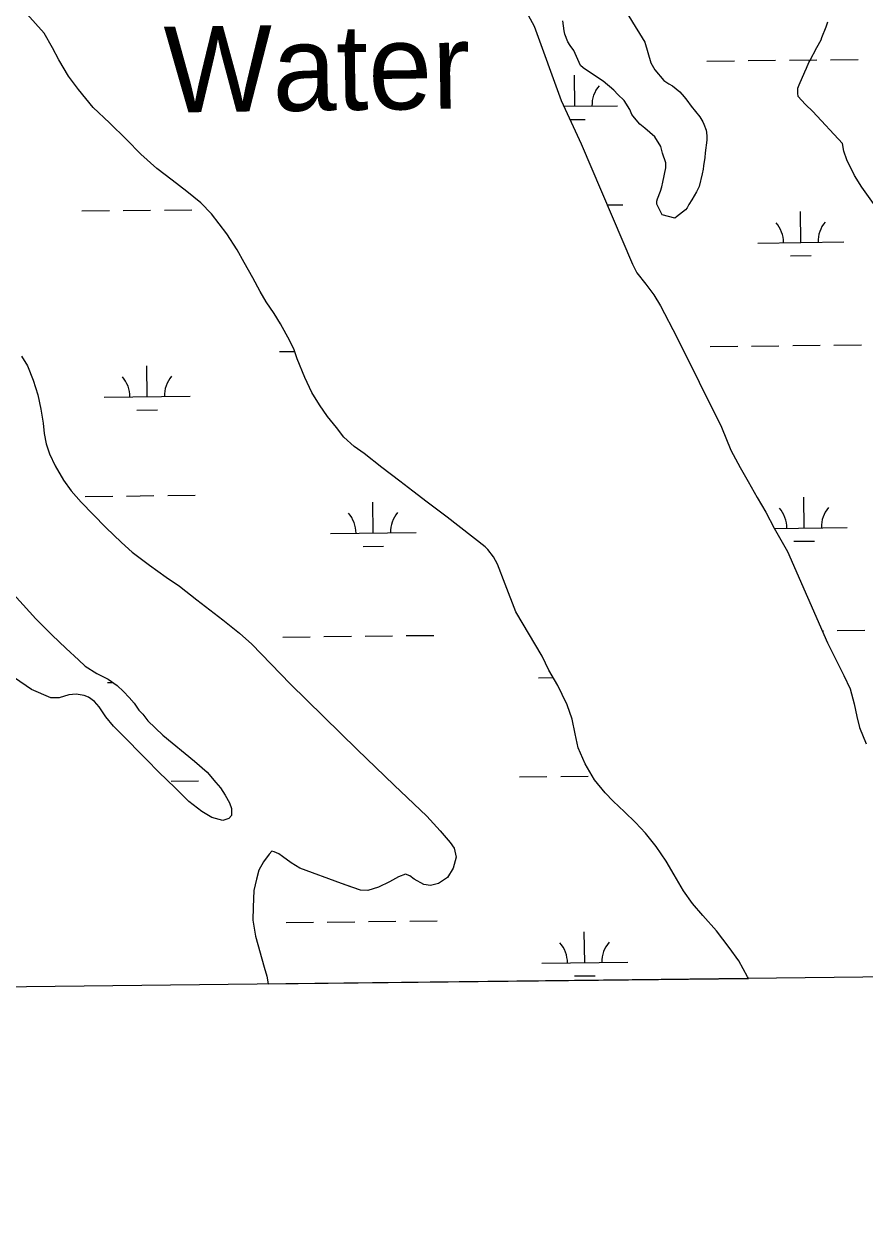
# Model space of a CAD drawing. Extents: x 3683613 to 3738215, y 469626 to 495384.
# Drawn here: x 3712781 to 3713760, y 475040 to 476452 of the extents above; entities that cross this region are included whole.
import ezdxf

# ---------------------------------------------------------------- set-up
doc = ezdxf.new("R2010")
doc.units = 0
for name, color, linetype in [('V-GRID-FRAM', 7, 'Continuous'), ('V-RIVR-IDEN', 7, 'Continuous'), ('V-SITE-VEGE', 7, 'Continuous'), ('V-TOPO-SHOR', 7, 'Continuous'), ('V-WETL-SWMP', 7, 'Continuous')]:
    doc.layers.add(name, color=color, linetype=linetype)

msp = doc.modelspace()

# ---------------------------------------------------------------- linework, layer by layer
at = {"layer": 'V-GRID-FRAM'}
msp.add_lwpolyline([(3687651.7, 493221.8), (3719350.3, 493590.7), (3719569.8, 475409.4), (3687855.3, 475040.3), (3687651.7, 493221.8)], dxfattribs=at)
at = {"layer": 'V-SITE-VEGE'}
for p, q in [((3713714.6, 476448.8), (3713716.7, 476454.7)), ((3713709.7, 476436.7), (3713714.6, 476448.8)), ((3713695.6, 476409.3), (3713703.9, 476425.1)), ((3713703.9, 476425.1), (3713708.8, 476433.7)), ((3713708.8, 476433.7), (3713709.7, 476436.7)), ((3713683, 476381.4), (3713689.8, 476396.7)), ((3713689.8, 476396.7), (3713691.5, 476400.9)), ((3713691.5, 476400.9), (3713694.4, 476407.3)), ((3713694.4, 476407.3), (3713695.6, 476409.3)), ((3713681.4, 476371.6), (3713681.6, 476377.5)), ((3713682.1, 476367.7), (3713681.4, 476371.6)), ((3713681.6, 476377.5), (3713683, 476381.4)), ((3713685.9, 476363.5), (3713682.1, 476367.7)), ((3713690.6, 476358.6), (3713685.9, 476363.5)), ((3713699, 476350.5), (3713690.6, 476358.6)), ((3713733.7, 476313.1), (3713699, 476350.5)), ((3713735.2, 476304.3), (3713733.7, 476313.1)), ((3713738.7, 476294.2), (3713735.2, 476304.3)), ((3713747.7, 476275.8), (3713738.7, 476294.2)), ((3713756.1, 476262.1), (3713747.7, 476275.8)), ((3713769.8, 476243.3), (3713756.1, 476262.1))]:
    msp.add_line(p, q, dxfattribs=at)
msp.add_lwpolyline([(3713477.3, 476473.5), (3713492, 476449.3), (3713497.2, 476441.4), (3713503.4, 476431.2), (3713510.4, 476406.9), (3713514.9, 476398.8), (3713525.6, 476386.5), (3713531.3, 476382.6), (3713535.5, 476380.2), (3713544.1, 476373.4), (3713549.3, 476367.3), (3713552.3, 476363.6), (3713557.5, 476356.7), (3713567.4, 476344), (3713570.9, 476338.1), (3713572.2, 476335.7), (3713574.7, 476328.6), (3713575.2, 476325.9), (3713575.5, 476321.4), (3713575.5, 476316.8), (3713573.6, 476302.2), (3713573.4, 476296.6), (3713571.7, 476287), (3713571.5, 476283.3), (3713570.1, 476277.6), (3713566.7, 476262.8), (3713563.6, 476256.7), (3713558.2, 476247.3), (3713554.8, 476241.8), (3713552.6, 476238.1), (3713550.7, 476235.9), (3713540.2, 476227.5), (3713538.2, 476226.2), (3713523.4, 476229.8), (3713517.4, 476242.3), (3713517.4, 476245.8), (3713518.1, 476248.7), (3713521.8, 476257.6), (3713523.2, 476262.5), (3713524.2, 476268), (3713527.7, 476284.5), (3713527.7, 476290.6), (3713523.9, 476301.7), (3713522.2, 476309.5), (3713514.9, 476321), (3713503.3, 476331), (3713497.6, 476335.4), (3713491.2, 476343), (3713488.2, 476346.9), (3713486, 476352.6), (3713479.2, 476363.1), (3713472.1, 476370.2), (3713467.1, 476375.3), (3713454.7, 476385.8), (3713448.1, 476390), (3713431.5, 476401.2), (3713428.3, 476403.8), (3713420.8, 476421.5), (3713416.6, 476427.4), (3713413.9, 476431.5), (3713410.4, 476440.6), (3713409.3, 476444.5), (3713408, 476456.1)], dxfattribs=at)
at = {"layer": 'V-TOPO-SHOR'}
for points in [[(3713317, 476555.5), (3713374.6, 476449.9), (3713406.1, 476363.1), (3713429.3, 476312.6), (3713489.2, 476172.6), (3713494, 476162.4), (3713504.4, 476149), (3713514, 476136.8), (3713521.6, 476123.8), (3713540.8, 476087.2), (3713592.6, 475982.7), (3713603.4, 475955.9), (3713614.6, 475935.4), (3713623.8, 475919.3), (3713634.3, 475900.7), (3713644.3, 475883.4), (3713653.9, 475864.9), (3713669.5, 475837.7), (3713716.1, 475731.2), (3713735.3, 475693), (3713742.6, 475677.6), (3713747.4, 475660.2), (3713750.3, 475645.2), (3713753.5, 475632.6), (3713761.2, 475613.7)], [(3713317.5, 475843.2), (3713273.3, 475877.7), (3713249.9, 475895), (3713233.2, 475907.9), (3713218.1, 475919.7), (3713197, 475935.7), (3713176.3, 475951.8), (3713164.8, 475960), (3713152.8, 475971), (3713144.1, 475982), (3713133.7, 475995), (3713124.5, 476008.4), (3713115.7, 476023), (3713107.3, 476040.3), (3713098.4, 476062), (3713094.8, 476072.7), (3713090, 476083.3), (3713079.2, 476103), (3713071.6, 476114.8), (3713062.4, 476128.6), (3713055.2, 476140.4), (3713046.8, 476156.6), (3713036.8, 476174.3), (3713028.4, 476189.3), (3713016.4, 476207.8), (3712998.8, 476231), (3712986.1, 476244), (3712969.8, 476257.3), (3712952.7, 476270.2), (3712935.2, 476284), (3712916.5, 476300.8), (3712899.7, 476317.7), (3712879.8, 476337), (3712860.7, 476355), (3712843.6, 476375.9), (3712832, 476391.6), (3712820.8, 476410.5), (3712813.6, 476424.7), (3712803.6, 476441.7), (3712783.6, 476464.1)], [(3712777.5, 476065.2), (3712784.3, 476053.8), (3712791.1, 476037.2), (3712796.4, 476020.3), (3712800, 476003.3), (3712802.5, 475987.2), (3712803.8, 475975.3), (3712806.2, 475963.1), (3712809.9, 475951.3), (3712816.7, 475937.5), (3712826.3, 475920.6), (3712835.4, 475908.4), (3712847, 475895.1), (3712860.9, 475880.6), (3712875.6, 475865.7), (3712893.9, 475848), (3712906.2, 475836.7), (3712926.4, 475821.8), (3712945.9, 475807.7), (3712961.3, 475797.2), (3712981.6, 475781.5), (3713011.7, 475758), (3713031.2, 475742.4), (3713045.5, 475729.8), (3713090.4, 475683.5), (3713168.3, 475607.1), (3713211.6, 475565.5), (3713249.4, 475529.1), (3713264.9, 475512.2), (3713276.8, 475498.5), (3713281.2, 475491.8), (3713283.7, 475481.5), (3713280.2, 475468.5), (3713273.6, 475457.8), (3713262.9, 475450.6), (3713253.9, 475448.6), (3713246, 475449.7), (3713234.9, 475455.9), (3713229.7, 475459.9), (3713224.6, 475461.8), (3713216.3, 475458.6), (3713206.1, 475452.6), (3713193.1, 475446.6), (3713180.9, 475442.6), (3713172.2, 475442.9), (3713161.1, 475446.8), (3713150, 475450.6), (3713101.7, 475468.5), (3713091.4, 475474.7), (3713081.5, 475482.1), (3713077.2, 475485.3), (3713071.6, 475487.6), (3713068.8, 475488.4), (3713065.7, 475484.8), (3713059.4, 475476.1), (3713054, 475466.2), (3713050.9, 475455.9), (3713047.8, 475442.8), (3713047.2, 475423.1), (3713046.9, 475408.1), (3713049.8, 475389.5), (3713059.9, 475353.3), (3713063.1, 475342.7), (3713064.6, 475333.7)], [(3713353.2, 475767.5), (3713340.7, 475799.5), (3713331.8, 475822.7), (3713327, 475831.4), (3713320.6, 475840.1), (3713317.5, 475843.2)], [(3712760.6, 475796.2), (3712794, 475759), (3712812.7, 475740.5), (3712829.5, 475724.8), (3712843.8, 475711.4), (3712851.7, 475704.2), (3712865.3, 475695.5), (3712878.3, 475688.9), (3712888.8, 475681.4), (3712896.1, 475674.5), (3712902.7, 475667.7), (3712908.8, 475660.8), (3712913.9, 475652.9), (3712918.6, 475647.9), (3712924.4, 475640.4), (3712942.1, 475623.5), (3712978.9, 475593.2), (3712993.8, 475580.6), (3713003.6, 475568.4), (3713009, 475562.2), (3713014.5, 475553.7), (3713019.6, 475544.9), (3713021.8, 475538.3), (3713021.8, 475536.4), (3713021.9, 475530.1), (3713018.7, 475526.6), (3713011.8, 475524.3), (3712999.2, 475527.7), (3712987.5, 475534.6), (3712972.3, 475546.5), (3712956.4, 475562.4), (3712937.4, 475580.6), (3712922.8, 475595.3), (3712912.3, 475605.9), (3712903.1, 475615.6), (3712894.2, 475624.4), (3712884.7, 475634.1), (3712875.8, 475645.1), (3712867.8, 475656.7), (3712862.4, 475663), (3712855.4, 475668), (3712850.4, 475669.8), (3712841.2, 475671.3), (3712832.7, 475670.6), (3712821.1, 475667.1), (3712811.6, 475667), (3712788.9, 475676.7), (3712769.2, 475690.4)], [(3713624.3, 475340.2), (3713623, 475342.2), (3713613, 475360.7), (3713601.8, 475376.1), (3713586.7, 475395.8), (3713571.1, 475413.4), (3713558.8, 475427.6), (3713548.4, 475442.2), (3713537.6, 475460.7), (3713528.4, 475476.8), (3713516.4, 475493.8), (3713504, 475509.5), (3713492.5, 475521.7), (3713479.7, 475534.2), (3713466.6, 475546.8), (3713457, 475556.6), (3713444.7, 475571.6), (3713433.9, 475590.1), (3713425.8, 475609), (3713422.2, 475625.2), (3713418.9, 475642.2), (3713412.8, 475658.8), (3713407.2, 475671), (3713402, 475681.6), (3713391.6, 475699.4), (3713384, 475715.5), (3713353.2, 475767.5)]]:
    msp.add_lwpolyline(points, dxfattribs=at)
at = {"layer": 'V-WETL-SWMP'}
for p, q in [((3713317, 476555.5), (3713374.6, 476449.9)), ((3712803.6, 476441.7), (3712783.6, 476464.1)), ((3712813.6, 476424.7), (3712803.6, 476441.7)), ((3713374.6, 476449.9), (3713406.1, 476363.1)), ((3712820.8, 476410.5), (3712813.6, 476424.7)), ((3712832, 476391.6), (3712820.8, 476410.5)), ((3713671.7, 476410.2), (3713703.7, 476410.5)), ((3713719.7, 476410.7), (3713751.7, 476411.1)), ((3713575.7, 476409), (3713607.7, 476409.4)), ((3713623.7, 476409.6), (3713655.7, 476410)), ((3712843.6, 476375.9), (3712832, 476391.6)), ((3713421.7, 476356.5), (3713421.3, 476392.5)), ((3712860.7, 476355), (3712843.6, 476375.9)), ((3712879.8, 476337), (3712860.7, 476355)), ((3713406.1, 476363.1), (3713429.3, 476312.6)), ((3713409.2, 476356.4), (3713471.7, 476357.1)), ((3713416.3, 476341), (3713433.9, 476341.2)), ((3712899.7, 476317.7), (3712879.8, 476337)), ((3712916.5, 476300.8), (3712899.7, 476317.7)), ((3713429.3, 476312.6), (3713489.2, 476172.6)), ((3712935.2, 476284), (3712916.5, 476300.8)), ((3712952.7, 476270.2), (3712935.2, 476284)), ((3712969.8, 476257.3), (3712952.7, 476270.2)), ((3712986.1, 476244), (3712969.8, 476257.3)), ((3712998.8, 476231), (3712986.1, 476244)), ((3713459.8, 476241.5), (3713477.7, 476241.7)), ((3712847.8, 476234.4), (3712879.8, 476234.8)), ((3712895.8, 476234.9), (3712927.8, 476235.3)), ((3712943.8, 476235.5), (3712975.8, 476235.9)), ((3713016.4, 476207.8), (3712998.8, 476231)), ((3713685.1, 476197.7), (3713684.6, 476233.7)), ((3713028.4, 476189.3), (3713016.4, 476207.8)), ((3713036.8, 476174.3), (3713028.4, 476189.3)), ((3713635.1, 476197.1), (3713735, 476198.3)), ((3713046.8, 476156.6), (3713036.8, 476174.3)), ((3713489.2, 476172.6), (3713494, 476162.4)), ((3713673.2, 476182.1), (3713697.2, 476182.4)), ((3713055.2, 476140.4), (3713046.8, 476156.6)), ((3713494, 476162.4), (3713504.4, 476149)), ((3713504.4, 476149), (3713514, 476136.8)), ((3713062.4, 476128.6), (3713055.2, 476140.4)), ((3713071.6, 476114.8), (3713062.4, 476128.6)), ((3713514, 476136.8), (3713521.6, 476123.8)), ((3713079.2, 476103), (3713071.6, 476114.8)), ((3713521.6, 476123.8), (3713540.8, 476087.2)), ((3713090, 476083.3), (3713079.2, 476103)), ((3713540.8, 476087.2), (3713592.6, 475982.7)), ((3713094.8, 476072.7), (3713090, 476083.3)), ((3713098.4, 476062), (3713094.8, 476072.7)), ((3713579.6, 476076.4), (3713611.6, 476076.8)), ((3713627.6, 476076.9), (3713659.6, 476077.3)), ((3713675.6, 476077.5), (3713707.6, 476077.9)), ((3713723.6, 476078.1), (3713755.6, 476078.4)), ((3712777.5, 476065.2), (3712784.3, 476053.8)), ((3713077.7, 476070.5), (3713095.5, 476070.7)), ((3713107.3, 476040.3), (3713098.4, 476062)), ((3712784.3, 476053.8), (3712791.1, 476037.2)), ((3712923.7, 476018), (3712923.3, 476054)), ((3712791.1, 476037.2), (3712796.4, 476020.3)), ((3713115.7, 476023), (3713107.3, 476040.3)), ((3712796.4, 476020.3), (3712800, 476003.3)), ((3712873.7, 476017.4), (3712973.7, 476018.6)), ((3713124.5, 476008.4), (3713115.7, 476023)), ((3712800, 476003.3), (3712802.5, 475987.2)), ((3712911.9, 476002.4), (3712935.9, 476002.7)), ((3713133.7, 475995), (3713124.5, 476008.4)), ((3712802.5, 475987.2), (3712803.8, 475975.3)), ((3713144.1, 475982), (3713133.7, 475995)), ((3712803.8, 475975.3), (3712806.2, 475963.1)), ((3713152.8, 475971), (3713144.1, 475982)), ((3713592.6, 475982.7), (3713603.4, 475955.9)), ((3712806.2, 475963.1), (3712809.9, 475951.3)), ((3713164.8, 475960), (3713152.8, 475971)), ((3713176.3, 475951.8), (3713164.8, 475960)), ((3712809.9, 475951.3), (3712816.7, 475937.5)), ((3713197, 475935.7), (3713176.3, 475951.8)), ((3713603.4, 475955.9), (3713614.6, 475935.4)), ((3712816.7, 475937.5), (3712826.3, 475920.6)), ((3713218.1, 475919.7), (3713197, 475935.7)), ((3713614.6, 475935.4), (3713623.8, 475919.3)), ((3712826.3, 475920.6), (3712835.4, 475908.4)), ((3713233.2, 475907.9), (3713218.1, 475919.7)), ((3713623.8, 475919.3), (3713634.3, 475900.7)), ((3712835.4, 475908.4), (3712847, 475895.1)), ((3712899.7, 475902.3), (3712931.7, 475902.7)), ((3712947.7, 475902.8), (3712979.7, 475903.2)), ((3713249.9, 475895), (3713233.2, 475907.9)), ((3712847, 475895.1), (3712860.9, 475880.6)), ((3712851.7, 475901.7), (3712883.7, 475902.1)), ((3713187, 475859.2), (3713186.6, 475895.2)), ((3713273.3, 475877.7), (3713249.9, 475895)), ((3713634.3, 475900.7), (3713644.3, 475883.4)), ((3713688.9, 475865), (3713688.5, 475901)), ((3712860.9, 475880.6), (3712875.6, 475865.7)), ((3713317.5, 475843.2), (3713273.3, 475877.7)), ((3713644.3, 475883.4), (3713653.9, 475864.9)), ((3712875.6, 475865.7), (3712893.9, 475848)), ((3713653.9, 475864.9), (3713669.5, 475837.7)), ((3713654, 475864.6), (3713738.9, 475865.6)), ((3712893.9, 475848), (3712906.2, 475836.7)), ((3713137.1, 475858.6), (3713237, 475859.8)), ((3713677.1, 475849.5), (3713701.1, 475849.7)), ((3712906.2, 475836.7), (3712926.4, 475821.8)), ((3713175.2, 475843.6), (3713199.2, 475843.9)), ((3713320.6, 475840.1), (3713317.5, 475843.2)), ((3713327, 475831.4), (3713320.6, 475840.1)), ((3713669.5, 475837.7), (3713716.1, 475731.2)), ((3712926.4, 475821.8), (3712945.9, 475807.7)), ((3713331.8, 475822.7), (3713327, 475831.4)), ((3713340.7, 475799.5), (3713331.8, 475822.7)), ((3712945.9, 475807.7), (3712961.3, 475797.2)), ((3712961.3, 475797.2), (3712981.6, 475781.5)), ((3713353.2, 475767.5), (3713340.7, 475799.5)), ((3712981.6, 475781.5), (3713011.7, 475758)), ((3713384, 475715.5), (3713353.2, 475767.5)), ((3713011.7, 475758), (3713031.2, 475742.4)), ((3713031.2, 475742.4), (3713045.5, 475729.8)), ((3713081.6, 475737.9), (3713113.6, 475738.3)), ((3713129.6, 475738.4), (3713161.6, 475738.8)), ((3713177.6, 475739), (3713209.6, 475739.4)), ((3713225.6, 475739.6), (3713257.6, 475739.9)), ((3713710, 475745.2), (3713711.5, 475745.2)), ((3713727.5, 475745.4), (3713759.5, 475745.8)), ((3713045.5, 475729.8), (3713090.4, 475683.5)), ((3713716.1, 475731.2), (3713735.3, 475693)), ((3713391.6, 475699.4), (3713384, 475715.5)), ((3713379.5, 475690.6), (3713396.6, 475690.8)), ((3713402, 475681.6), (3713391.6, 475699.4)), ((3713735.3, 475693), (3713742.6, 475677.6)), ((3712877.6, 475684.8), (3712884, 475684.8)), ((3713090.4, 475683.5), (3713168.3, 475607.1)), ((3713407.2, 475671), (3713402, 475681.6)), ((3713742.6, 475677.6), (3713747.4, 475660.2)), ((3713412.8, 475658.8), (3713407.2, 475671)), ((3713418.9, 475642.2), (3713412.8, 475658.8)), ((3713747.4, 475660.2), (3713750.3, 475645.2)), ((3713422.2, 475625.2), (3713418.9, 475642.2)), ((3713750.3, 475645.2), (3713753.5, 475632.6)), ((3713425.8, 475609), (3713422.2, 475625.2)), ((3713753.5, 475632.6), (3713761.2, 475613.7)), ((3713168.3, 475607.1), (3713211.6, 475565.5)), ((3713433.9, 475590.1), (3713425.8, 475609)), ((3713444.7, 475571.6), (3713433.9, 475590.1)), ((3712951.6, 475570.2), (3712983.5, 475570.6)), ((3713211.6, 475565.5), (3713249.4, 475529.1)), ((3713357.4, 475574.9), (3713389.4, 475575.3)), ((3713405.4, 475575.5), (3713437.4, 475575.8)), ((3713457, 475556.6), (3713444.7, 475571.6)), ((3713466.6, 475546.8), (3713457, 475556.6)), ((3713479.7, 475534.2), (3713466.6, 475546.8)), ((3713249.4, 475529.1), (3713264.9, 475512.2)), ((3713492.5, 475521.7), (3713479.7, 475534.2)), ((3713504, 475509.5), (3713492.5, 475521.7)), ((3713264.9, 475512.2), (3713276.8, 475498.5)), ((3713516.4, 475493.8), (3713504, 475509.5)), ((3713276.8, 475498.5), (3713281.2, 475491.8)), ((3713528.4, 475476.8), (3713516.4, 475493.8)), ((3713065.7, 475484.8), (3713059.4, 475476.1)), ((3713068.8, 475488.4), (3713065.7, 475484.8)), ((3713071.6, 475487.6), (3713068.8, 475488.4)), ((3713077.2, 475485.3), (3713071.6, 475487.6)), ((3713081.5, 475482.1), (3713077.2, 475485.3)), ((3713091.4, 475474.7), (3713081.5, 475482.1)), ((3713283.7, 475481.5), (3713280.2, 475468.5)), ((3713281.2, 475491.8), (3713283.7, 475481.5)), ((3713054, 475466.2), (3713050.9, 475455.9)), ((3713059.4, 475476.1), (3713054, 475466.2)), ((3713101.7, 475468.5), (3713091.4, 475474.7)), ((3713150, 475450.6), (3713101.7, 475468.5)), ((3713280.2, 475468.5), (3713273.6, 475457.8)), ((3713537.6, 475460.7), (3713528.4, 475476.8)), ((3713050.9, 475455.9), (3713047.8, 475442.8)), ((3713172.2, 475442.9), (3713150, 475450.6)), ((3713206.1, 475452.6), (3713193.1, 475446.6)), ((3713216.3, 475458.6), (3713206.1, 475452.6)), ((3713224.6, 475461.8), (3713216.3, 475458.6)), ((3713229.7, 475459.9), (3713224.6, 475461.8)), ((3713234.9, 475455.9), (3713229.7, 475459.9)), ((3713246, 475449.7), (3713234.9, 475455.9)), ((3713262.9, 475450.6), (3713253.9, 475448.6)), ((3713273.6, 475457.8), (3713262.9, 475450.6)), ((3713548.4, 475442.2), (3713537.6, 475460.7)), ((3713047.8, 475442.8), (3713047.2, 475423.1)), ((3713180.9, 475442.6), (3713172.2, 475442.9)), ((3713193.1, 475446.6), (3713180.9, 475442.6)), ((3713253.9, 475448.6), (3713246, 475449.7)), ((3713558.8, 475427.6), (3713548.4, 475442.2)), ((3713047.2, 475423.1), (3713046.9, 475408.1)), ((3713571.1, 475413.4), (3713558.8, 475427.6)), ((3713046.9, 475408.1), (3713049.8, 475389.5)), ((3713586.7, 475395.8), (3713571.1, 475413.4)), ((3713085.5, 475405.2), (3713117.5, 475405.6)), ((3713133.5, 475405.8), (3713165.5, 475406.2)), ((3713181.5, 475406.4), (3713213.5, 475406.7)), ((3713229.5, 475406.9), (3713261.5, 475407.3)), ((3713433.4, 475358.5), (3713432.9, 475394.5)), ((3713601.8, 475376.1), (3713586.7, 475395.8)), ((3713049.8, 475389.5), (3713059.9, 475353.3)), ((3713613, 475360.7), (3713601.8, 475376.1)), ((3713059.9, 475353.3), (3713063.1, 475342.7)), ((3713383.4, 475358), (3713483.4, 475359.1)), ((3713623, 475342.2), (3713613, 475360.7)), ((3713063.1, 475342.7), (3713064.6, 475333.7)), ((3713064.6, 475333.7), (3713624.3, 475340.2)), ((3713421.5, 475343), (3713445.5, 475343.3)), ((3713624.3, 475340.2), (3713623, 475342.2))]:
    msp.add_line(p, q, dxfattribs=at)
for points in [[(3712760.6, 475796.2), (3712794, 475759), (3712812.7, 475740.5), (3712829.5, 475724.8), (3712843.8, 475711.4), (3712851.7, 475704.2), (3712865.3, 475695.5), (3712878.3, 475688.9), (3712888.8, 475681.4), (3712896.1, 475674.5), (3712902.7, 475667.7), (3712908.8, 475660.8), (3712913.9, 475652.9), (3712918.6, 475647.9), (3712924.4, 475640.4), (3712942.1, 475623.5), (3712978.9, 475593.2), (3712993.8, 475580.6), (3713003.6, 475568.4)], [(3713003.6, 475568.4), (3713009, 475562.2), (3713014.5, 475553.7), (3713019.6, 475544.9), (3713021.8, 475538.3), (3713021.8, 475536.4), (3713021.9, 475530.1), (3713018.7, 475526.6), (3713011.8, 475524.3), (3712999.2, 475527.7), (3712987.5, 475534.6), (3712972.3, 475546.5), (3712956.4, 475562.4), (3712937.4, 475580.6), (3712922.8, 475595.3), (3712912.3, 475605.9), (3712903.1, 475615.6), (3712894.2, 475624.4), (3712884.7, 475634.1), (3712875.8, 475645.1), (3712867.8, 475656.7), (3712862.4, 475663), (3712855.4, 475668), (3712850.4, 475669.8), (3712841.2, 475671.3), (3712832.7, 475670.6), (3712821.1, 475667.1), (3712811.6, 475667), (3712788.9, 475676.7), (3712769.2, 475690.4)]]:
    msp.add_lwpolyline(points, dxfattribs=at)
for centre, start, end in [((3713477, 476357.6), 139.8949, 181.4385), ((3713629.8, 476197.5), 359.8949, 41.4385), ((3713740.3, 476198.8), 139.8949, 181.4385), ((3712868.5, 476017.8), 359.8949, 41.4385), ((3712979, 476019.1), 139.8949, 181.4385), ((3713633.7, 475864.9), 359.8949, 41.4385), ((3713744.2, 475866.2), 139.8949, 181.4385), ((3713131.8, 475859), 359.8949, 41.4385), ((3713242.3, 475860.3), 139.8949, 181.4385), ((3713378.1, 475358.4), 359.8949, 41.4385), ((3713488.6, 475359.7), 139.8949, 181.4385)]:
    msp.add_arc(centre, 35.2, start, end, dxfattribs=at)

# ---------------------------------------------------------------- texts
at = {"layer": 'V-RIVR-IDEN'}
msp.add_text('Water', height=100, rotation=0.7994, dxfattribs=at).set_placement((3712944.1, 476349))

doc.saveas('drawing.dxf')
